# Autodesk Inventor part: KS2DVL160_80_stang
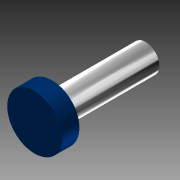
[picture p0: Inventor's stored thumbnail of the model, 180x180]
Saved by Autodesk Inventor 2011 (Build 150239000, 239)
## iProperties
Created: 2010-11
Document SubType Name: Modeling
Designer: TB
Mass: 161.233 g
Surface Area: 236.814 cm^2
Volume: 161.233 cm^3
Density: 1 g/cm^3
Author: TB
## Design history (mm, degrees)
sketch "Sketch2"
  geometry: L1 (-35, -3)-(-35, 3) reference; L2 (-35, -9)-(-35, 9) reference; L3 (-35, 40)-(-358, 40); L4 (-358, 40)-(-358, 0); L5 (-358, 0)-(-35, 0); L6 (-35, 0)-(-35, 40); L7 (-358, 40)-(-306, 40); L8 (-306, 40)-(-306, 80); L9 (-306, 80)-(-358, 80); L10 (-358, 80)-(-358, 40); 1 further point
  constraints: 16 end point, 4 parallel, 2 horizontal, 2 perpendicular, 1 midpoint
  dimensions: "Dia" = 80 diameter of L3 L5; "d3" = 323 distance of L3.start L3.end (computed from Slaglengde, Forlengelse_rør); "StempelDia" = 160 diameter of L9 L5; "StempelLengde" = 52 distance of L8.end L9.end
revolve "Revolution1" sketch "Sketch2" stored, may be unused: angle "d6" = 90 deg
fillet "Fillet1" dims "d7" = 2
sketch "Sketch3"
  geometry: L1 (-358, -78)-(-358, 78) reference; L2 (-358, 0)-(-358.01, 0); L3 (-358, 0)-(-358, 0.01); A1 r 0.01 centre (-358, 0) between (-358, 0.01) and (-358.01, 0); 1 further point
  constraints: 4 end point, 2 point on circle, 1 centre point, 1 midpoint, 1 perpendicular, 1 point on line
  dimensions: "d8" = 0.01 distance of L2.start L2.end; "d9" = 0.01 distance of L2.start L3.end (= d8); "d10" = 0.01 radius of A1 (= d8)
revolve "Revolution2" sketch "Sketch3" stored, may be unused: angle "d11" = 90 deg
body "Solid1"
node "Projected Loop2"
other parameters: "Forlengelse_rør" = 0
